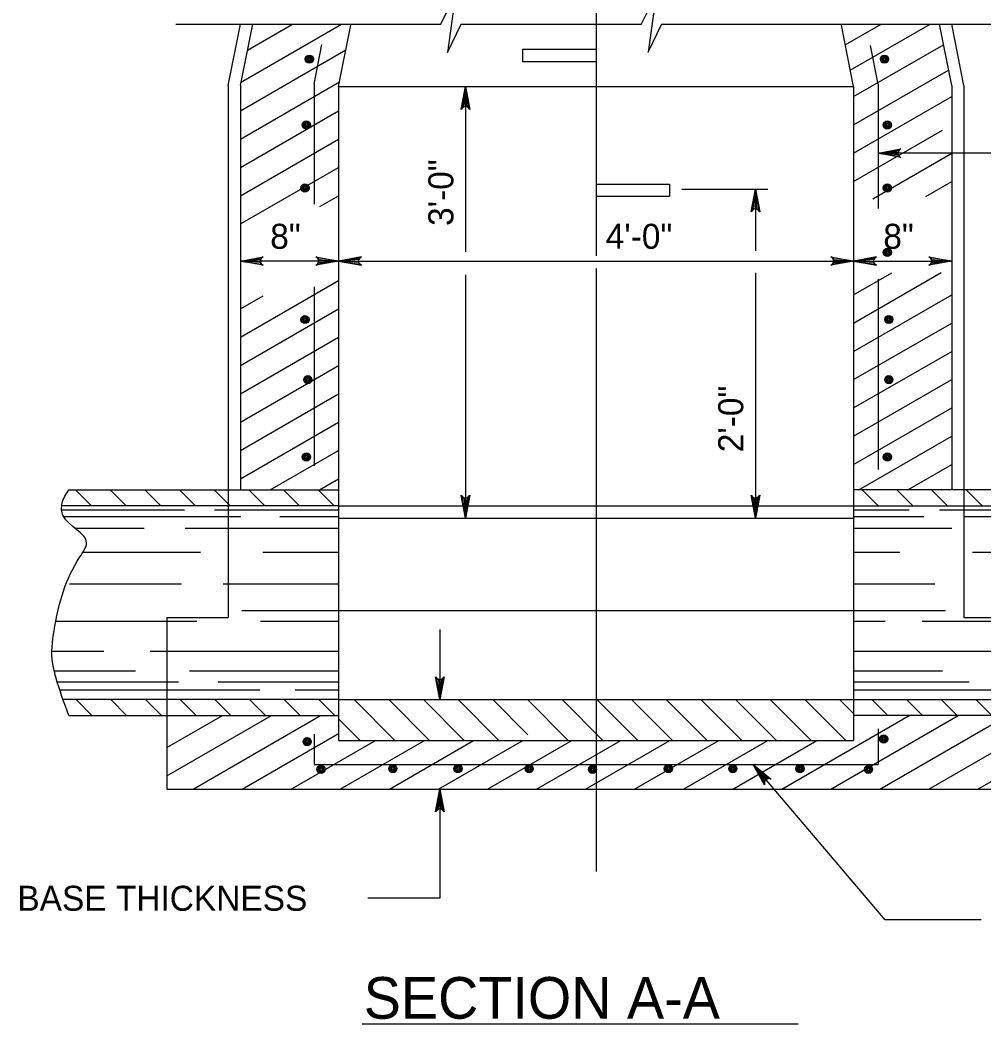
# Model space of a CAD drawing. Extents: x 0.9 to 8, y -0.9 to 9.3.
# Drawn here: x 1.252 to 3.564, y 1.04 to 3.449 of the extents above; entities that cross this region are included whole.
import ezdxf

# ---------------------------------------------------------------- set-up
doc = ezdxf.new("R2010")
doc.units = 0
for name, color, linetype in [('DETL-DIMS', 7, 'Continuous'), ('DETL-LINE', 7, 'Continuous'), ('DETL-NOTE', 7, 'Continuous'), ('DETL-PATT', 7, 'Continuous'), ('DETL-TITL', 7, 'Continuous')]:
    doc.layers.add(name, color=color, linetype=linetype)

msp = doc.modelspace()

# ---------------------------------------------------------------- linework, layer by layer
at = {"layer": 'DETL-DIMS'}
for p, q in [((2.6337, 4.5047), (2.6337, 2.8837)), ((2.3208, 3.2898), (2.3208, 2.8934)), ((3.7703, 3.1298), (3.3102, 3.1298)), ((2.8396, 3.0438), (3.0455, 3.0438)), ((3.0161, 3.0438), (3.0161, 2.8954)), ((2.0161, 2.871), (1.7808, 2.871)), ((2.0161, 2.871), (3.2514, 2.871)), ((3.2514, 2.871), (3.4867, 2.871)), ((2.6337, 2.8532), (2.6337, 1.4062)), ((2.3208, 2.8379), (2.3208, 2.2544)), ((3.0161, 2.8426), (3.0161, 2.2544)), ((1.7843, 2.0325), (3.4722, 2.0325)), ((2.2591, 1.9865), (2.2591, 1.8187)), ((3.3274, 1.29), (3.0102, 1.6628)), ((2.2591, 1.604), (2.2591, 1.3419)), ((2.2591, 1.3419), (2.0865, 1.3419)), ((3.5574, 1.29), (3.3274, 1.29))]:
    msp.add_line(p, q, dxfattribs=at)
for points in [[(2.3208, 3.2898), (2.3311, 3.2349), (2.3281, 3.2392), (2.3245, 3.2413), (2.3208, 3.242), (2.3171, 3.2413), (2.3134, 3.2392), (2.3105, 3.2349), (2.3208, 3.2898), (2.3134, 3.2392), (2.3171, 3.2413), (2.3208, 3.2898), (2.3208, 3.242), (2.3245, 3.2413), (2.3208, 3.2898), (2.3281, 3.2392)], [(3.3102, 3.1298), (3.365, 3.14), (3.3608, 3.1371), (3.3586, 3.1334), (3.358, 3.1298), (3.3586, 3.1261), (3.3608, 3.1224), (3.365, 3.1195), (3.3102, 3.1298), (3.3608, 3.1224), (3.3586, 3.1261), (3.3102, 3.1298), (3.358, 3.1298), (3.3586, 3.1334), (3.3102, 3.1298), (3.3608, 3.1371)], [(3.0161, 3.0438), (3.0264, 2.9889), (3.0234, 2.9932), (3.0197, 2.9953), (3.0161, 2.996), (3.0124, 2.9953), (3.0087, 2.9932), (3.0058, 2.9889), (3.0161, 3.0438), (3.0087, 2.9932), (3.0124, 2.9953), (3.0161, 3.0438), (3.0161, 2.996), (3.0197, 2.9953), (3.0161, 3.0438), (3.0234, 2.9932)], [(1.7808, 2.871), (1.8356, 2.8813), (1.8314, 2.8784), (1.8292, 2.8747), (1.8286, 2.871), (1.8292, 2.8674), (1.8314, 2.8637), (1.8356, 2.8608), (1.7808, 2.871), (1.8314, 2.8637), (1.8292, 2.8674), (1.7808, 2.871), (1.8286, 2.871), (1.8292, 2.8747), (1.7808, 2.871), (1.8314, 2.8784)], [(2.0161, 2.871), (1.9612, 2.8608), (1.9655, 2.8637), (1.9676, 2.8674), (1.9683, 2.871), (1.9676, 2.8747), (1.9655, 2.8784), (1.9612, 2.8813), (2.0161, 2.871), (1.9655, 2.8784), (1.9676, 2.8747), (2.0161, 2.871), (1.9683, 2.871), (1.9676, 2.8674), (2.0161, 2.871), (1.9655, 2.8637)], [(2.0161, 2.871), (2.0709, 2.8608), (2.0667, 2.8637), (2.0645, 2.8674), (2.0639, 2.871), (2.0645, 2.8747), (2.0667, 2.8784), (2.0709, 2.8813), (2.0161, 2.871), (2.0667, 2.8784), (2.0645, 2.8747), (2.0161, 2.871), (2.0639, 2.871), (2.0645, 2.8674), (2.0161, 2.871), (2.0667, 2.8637)], [(3.2514, 2.871), (3.1965, 2.8608), (3.2008, 2.8637), (3.2029, 2.8674), (3.2036, 2.871), (3.2029, 2.8747), (3.2008, 2.8784), (3.1965, 2.8813), (3.2514, 2.871), (3.2008, 2.8784), (3.2029, 2.8747), (3.2514, 2.871), (3.2036, 2.871), (3.2029, 2.8674), (3.2514, 2.871), (3.2008, 2.8637)], [(3.2514, 2.871), (3.3062, 2.8608), (3.302, 2.8637), (3.2998, 2.8674), (3.2992, 2.871), (3.2998, 2.8747), (3.302, 2.8784), (3.3062, 2.8813), (3.2514, 2.871), (3.302, 2.8784), (3.2998, 2.8747), (3.2514, 2.871), (3.2992, 2.871), (3.2998, 2.8674), (3.2514, 2.871), (3.302, 2.8637)], [(3.4867, 2.871), (3.4318, 2.8608), (3.4361, 2.8637), (3.4382, 2.8674), (3.4389, 2.871), (3.4382, 2.8747), (3.4361, 2.8784), (3.4318, 2.8813), (3.4867, 2.871), (3.4361, 2.8784), (3.4382, 2.8747), (3.4867, 2.871), (3.4389, 2.871), (3.4382, 2.8674), (3.4867, 2.871), (3.4361, 2.8637)], [(2.3208, 2.2544), (2.3105, 2.3093), (2.3134, 2.305), (2.3171, 2.3029), (2.3208, 2.3022), (2.3245, 2.3029), (2.3281, 2.305), (2.3311, 2.3093), (2.3208, 2.2544), (2.3281, 2.305), (2.3245, 2.3029), (2.3208, 2.2544), (2.3208, 2.3022), (2.3171, 2.3029), (2.3208, 2.2544), (2.3134, 2.305)], [(3.0161, 2.2544), (3.0058, 2.3093), (3.0087, 2.305), (3.0124, 2.3029), (3.0161, 2.3022), (3.0197, 2.3029), (3.0234, 2.305), (3.0264, 2.3093), (3.0161, 2.2544), (3.0234, 2.305), (3.0197, 2.3029), (3.0161, 2.2544), (3.0161, 2.3022), (3.0124, 2.3029), (3.0161, 2.2544), (3.0087, 2.305)], [(2.2591, 1.8187), (2.2489, 1.8735), (2.2518, 1.8693), (2.2555, 1.8671), (2.2591, 1.8665), (2.2628, 1.8671), (2.2665, 1.8693), (2.2694, 1.8735), (2.2591, 1.8187), (2.2665, 1.8693), (2.2628, 1.8671), (2.2591, 1.8187), (2.2591, 1.8665), (2.2555, 1.8671), (2.2591, 1.8187), (2.2518, 1.8693)], [(3.0102, 1.6628), (3.0536, 1.6277), (3.0486, 1.629), (3.0444, 1.6283), (3.0412, 1.6264), (3.0388, 1.6235), (3.0374, 1.6195), (3.0379, 1.6144), (3.0102, 1.6628), (3.0374, 1.6195), (3.0388, 1.6235), (3.0102, 1.6628), (3.0412, 1.6264), (3.0444, 1.6283), (3.0102, 1.6628), (3.0486, 1.629)], [(2.2591, 1.604), (2.2694, 1.5491), (2.2665, 1.5534), (2.2628, 1.5555), (2.2591, 1.5562), (2.2555, 1.5555), (2.2518, 1.5534), (2.2489, 1.5491), (2.2591, 1.604), (2.2518, 1.5534), (2.2555, 1.5555), (2.2591, 1.604), (2.2591, 1.5562), (2.2628, 1.5555), (2.2591, 1.604), (2.2665, 1.5534)]]:
    msp.add_lwpolyline(points, dxfattribs=at)
at = {"layer": 'DETL-LINE'}
for p, q in [((1.626, 3.4397), (2.2612, 3.4397)), ((1.7514, 3.2927), (1.7808, 3.4397)), ((1.7808, 3.2927), (1.8102, 3.4397)), ((2.0161, 3.2898), (2.0455, 3.4368)), ((2.3097, 3.4397), (2.7427, 3.4397)), ((2.7912, 3.4397), (3.6474, 3.4397)), ((3.2514, 3.2898), (3.222, 3.4368)), ((3.4867, 3.2927), (3.4572, 3.4397)), ((3.5161, 3.2927), (3.4867, 3.4397)), ((1.9572, 3.2956), (1.9763, 3.391)), ((2.4572, 3.3795), (2.4572, 3.35)), ((2.4572, 3.3795), (2.6337, 3.3795)), ((2.6337, 3.3795), (2.6337, 3.35)), ((3.3102, 3.2956), (3.2916, 3.3883)), ((2.4572, 3.35), (2.6337, 3.35)), ((1.7514, 3.2927), (1.7514, 2.3221)), ((1.7808, 3.2927), (1.7808, 2.3221)), ((1.9572, 3.2956), (1.9572, 3.0072)), ((2.0161, 3.2898), (2.0161, 1.7206)), ((2.0161, 3.2898), (3.2514, 3.2898)), ((3.2514, 3.2898), (3.2514, 1.7206)), ((3.3102, 3.2956), (3.3102, 2.997)), ((3.4867, 3.2927), (3.4867, 2.3221)), ((3.5161, 3.2927), (3.5161, 2.3221)), ((2.6337, 3.0559), (2.8102, 3.0559)), ((2.6337, 3.0559), (2.6337, 3.0265)), ((2.8102, 3.0559), (2.8102, 3.0265)), ((2.6337, 3.0265), (2.8102, 3.0265)), ((3.3102, 2.8276), (3.3102, 2.371)), ((1.9572, 2.8093), (1.9572, 2.3798)), ((1.369, 2.3221), (2.0161, 2.3221)), ((1.7514, 2.3221), (1.7514, 2.0157)), ((3.8992, 2.3221), (3.2514, 2.3221)), ((3.5161, 2.3221), (3.5161, 2.0157)), ((2.0161, 2.2839), (1.3513, 2.2839)), ((2.0161, 2.2839), (3.2514, 2.2839)), ((3.2514, 2.2839), (3.9149, 2.2839)), ((2.0161, 2.2544), (3.2514, 2.2544)), ((1.6043, 2.0157), (1.7514, 2.0157)), ((1.6043, 2.0157), (1.6043, 1.7804)), ((3.5161, 2.0157), (3.6631, 2.0157)), ((2.0161, 1.8187), (1.3562, 1.8187)), ((2.0161, 1.8187), (3.2514, 1.8187)), ((3.2514, 1.8187), (3.9113, 1.8187)), ((1.369, 1.7804), (2.0161, 1.7804)), ((1.6043, 1.7804), (1.6043, 1.604)), ((3.8984, 1.7804), (3.2514, 1.7804)), ((1.9572, 1.7354), (1.9572, 1.6628)), ((3.3102, 1.7487), (3.3102, 1.6628)), ((2.0161, 1.7206), (3.2514, 1.7206)), ((1.9572, 1.6628), (3.3102, 1.6628)), ((1.6043, 1.604), (3.6631, 1.604))]:
    msp.add_line(p, q, dxfattribs=at)
for points in [[(2.2612, 3.4398), (2.2962, 3.5113), (2.2772, 3.3714), (2.3098, 3.4398)], [(2.743, 3.4404), (2.778, 3.5118), (2.759, 3.3719), (2.7915, 3.4404)]]:
    msp.add_lwpolyline(points, dxfattribs=at)
for centre, radius in [((1.9458, 3.3556), 0.0098), ((1.9458, 3.3556), 0.00735), ((1.9458, 3.3556), 0.0049), ((1.9458, 3.3556), 0.00245), ((3.3256, 3.3556), 0.0098), ((3.3256, 3.3556), 0.00735), ((3.3256, 3.3556), 0.0049), ((3.3256, 3.3556), 0.00245), ((1.9389, 3.1976), 0.0098), ((1.9389, 3.1976), 0.00735), ((3.3324, 3.1976), 0.0098), ((3.3324, 3.1976), 0.00735), ((1.9389, 3.1976), 0.0049), ((1.9389, 3.1976), 0.00245), ((3.3324, 3.1976), 0.0049), ((3.3324, 3.1976), 0.00245), ((1.9355, 3.0465), 0.0098), ((1.9355, 3.0465), 0.00735), ((1.9355, 3.0465), 0.0049), ((1.9355, 3.0465), 0.00245), ((3.3324, 3.0465), 0.0098), ((3.3324, 3.0465), 0.00735), ((3.3324, 3.0465), 0.0049), ((3.3324, 3.0465), 0.00245), ((3.3324, 2.892), 0.0098), ((3.3324, 2.892), 0.00735), ((3.3324, 2.892), 0.0049), ((3.3324, 2.892), 0.00245), ((1.9355, 2.7306), 0.0098), ((1.9355, 2.7306), 0.00735), ((1.9355, 2.7306), 0.0049), ((1.9355, 2.7306), 0.00245), ((3.3359, 2.7306), 0.0098), ((3.3359, 2.7306), 0.00735), ((3.3359, 2.7306), 0.0049), ((3.3359, 2.7306), 0.00245), ((1.9424, 2.5863), 0.0098), ((1.9424, 2.5863), 0.00735), ((1.9424, 2.5863), 0.0049), ((1.9424, 2.5863), 0.00245), ((3.3359, 2.5863), 0.0098), ((3.3359, 2.5863), 0.00735), ((3.3359, 2.5863), 0.0049), ((3.3359, 2.5863), 0.00245), ((1.9389, 2.4009), 0.0098), ((3.3324, 2.4009), 0.0098), ((1.9389, 2.4009), 0.00735), ((1.9389, 2.4009), 0.0049), ((1.9389, 2.4009), 0.00245), ((3.3324, 2.4009), 0.00735), ((3.3324, 2.4009), 0.0049), ((3.3324, 2.4009), 0.00245), ((1.9408, 1.7178), 0.0098), ((1.9408, 1.7178), 0.00735), ((1.9408, 1.7178), 0.0049), ((1.9408, 1.7178), 0.00245), ((3.3237, 1.7241), 0.0098), ((3.3237, 1.7241), 0.00735), ((3.3237, 1.7241), 0.0049), ((3.3237, 1.7241), 0.00245), ((2.1462, 1.6529), 0.0098), ((2.3027, 1.6529), 0.0098), ((2.4734, 1.6529), 0.0098), ((2.8069, 1.6529), 0.0098), ((2.9617, 1.6529), 0.0098), ((3.123, 1.6529), 0.0098), ((1.974, 1.6513), 0.0098), ((1.974, 1.6513), 0.00735), ((1.974, 1.6513), 0.0049), ((1.974, 1.6513), 0.00245), ((2.1462, 1.6529), 0.00735), ((2.1462, 1.6529), 0.0049), ((2.1462, 1.6529), 0.00245), ((2.3027, 1.6529), 0.00735), ((2.3027, 1.6529), 0.0049), ((2.3027, 1.6529), 0.00245), ((2.4734, 1.6529), 0.00735), ((2.4734, 1.6529), 0.0049), ((2.4734, 1.6529), 0.00245), ((2.6251, 1.6513), 0.0098), ((2.6251, 1.6513), 0.00735), ((2.6251, 1.6513), 0.0049), ((2.6251, 1.6513), 0.00245), ((2.8069, 1.6529), 0.00735), ((2.8069, 1.6529), 0.0049), ((2.8069, 1.6529), 0.00245), ((2.9617, 1.6529), 0.00735), ((2.9617, 1.6529), 0.0049), ((2.9617, 1.6529), 0.00245), ((3.123, 1.6529), 0.00735), ((3.123, 1.6529), 0.0049), ((3.123, 1.6529), 0.00245), ((3.2873, 1.6513), 0.0098), ((3.2873, 1.6513), 0.00735), ((3.2873, 1.6513), 0.0049), ((3.2873, 1.6513), 0.00245)]:
    msp.add_circle(centre, radius, dxfattribs=at)
msp.add_spline([(1.369, 1.7804), (1.3381, 1.8724), (1.3293, 1.9149), (1.3356, 1.9949), (1.3956, 2.1612), (1.4118, 2.1949), (1.3556, 2.2599), (1.3531, 2.2899), (1.369, 2.3221)], degree=3, dxfattribs=at)
at = {"layer": 'DETL-PATT'}
for p, q in [((1.7808, 3.2996), (2.0235, 3.4397)), ((1.7977, 3.3773), (1.9059, 3.4397)), ((3.2313, 3.3899), (3.3176, 3.4397)), ((3.2435, 3.329), (3.4353, 3.4397)), ((1.7808, 3.2317), (2.0337, 3.3777)), ((3.2514, 3.2656), (3.4672, 3.3902)), ((3.2514, 3.1977), (3.4793, 3.3293)), ((1.7808, 3.1638), (2.0183, 3.3009)), ((3.2514, 3.1298), (3.4867, 3.2656)), ((1.7808, 3.0958), (2.0161, 3.2317)), ((3.2514, 3.0619), (3.4647, 3.185)), ((1.7808, 3.0279), (2.0161, 3.1638)), ((3.2978, 3.0207), (3.4867, 3.1298)), ((1.7808, 2.96), (2.0161, 3.0958)), ((3.4246, 3.0261), (3.4867, 3.0619)), ((1.9713, 3.0021), (2.0161, 3.0279)), ((3.2514, 2.7223), (3.4615, 2.8436)), ((3.2514, 2.7902), (3.3428, 2.843)), ((1.7808, 2.6883), (2.0161, 2.8241)), ((1.7808, 2.7562), (1.8353, 2.7877)), ((3.2514, 2.6543), (3.4867, 2.7902)), ((1.7808, 2.6204), (2.0161, 2.7562)), ((3.2514, 2.5864), (3.4867, 2.7223)), ((1.7808, 2.5524), (2.0161, 2.6883)), ((3.2514, 2.5185), (3.4867, 2.6543)), ((1.7808, 2.4845), (2.0161, 2.6204)), ((3.2514, 2.4506), (3.4867, 2.5864)), ((1.7808, 2.4166), (2.0161, 2.5524)), ((3.2514, 2.3826), (3.4867, 2.5185)), ((1.7808, 2.3487), (2.0161, 2.4845)), ((3.2641, 2.3221), (3.4867, 2.4506)), ((1.8524, 2.3221), (2.0161, 2.4166)), ((3.3818, 2.3221), (3.4867, 2.3826)), ((1.97, 2.3221), (2.0161, 2.3487)), ((1.3849, 2.3221), (1.4232, 2.2839)), ((1.4681, 2.3221), (1.5064, 2.2839)), ((1.5513, 2.3221), (1.5896, 2.2839)), ((1.6345, 2.3221), (1.6727, 2.2839)), ((1.7177, 2.3221), (1.7559, 2.2839)), ((1.8009, 2.3221), (1.8391, 2.2839)), ((1.8841, 2.3221), (1.9223, 2.2839)), ((1.9673, 2.3221), (2.0055, 2.2839)), ((3.2722, 2.3221), (3.3105, 2.2839)), ((3.3554, 2.3221), (3.3937, 2.2839)), ((3.4386, 2.3221), (3.4768, 2.2839)), ((3.5218, 2.3221), (3.56, 2.2839)), ((1.3518, 2.2742), (1.6465, 2.2742)), ((1.7185, 2.2742), (2.0161, 2.2742)), ((3.2514, 2.2742), (3.3847, 2.2742)), ((3.4578, 2.2742), (3.915, 2.2742)), ((1.3561, 2.2583), (1.7818, 2.2583)), ((1.8749, 2.2583), (2.0161, 2.2583)), ((3.2514, 2.2583), (3.4195, 2.2583)), ((3.5169, 2.2583), (3.9113, 2.2583)), ((1.3853, 2.2302), (1.5499, 2.2302)), ((1.6483, 2.2302), (2.0161, 2.2302)), ((3.2514, 2.2302), (3.4868, 2.2302)), ((1.4008, 2.1722), (1.6851, 2.1722)), ((1.8345, 2.1722), (2.0161, 2.1722)), ((3.2514, 2.1722), (3.3627, 2.1722)), ((3.5366, 2.1722), (3.8647, 2.1722)), ((1.3704, 2.0966), (1.6395, 2.0966)), ((1.7396, 2.0966), (2.0161, 2.0966)), ((3.2514, 2.0966), (3.4462, 2.0966)), ((1.3391, 2.007), (1.6764, 2.007)), ((1.8292, 2.007), (2.0161, 2.007)), ((3.2514, 2.007), (3.3268, 2.007)), ((3.416, 2.007), (3.7372, 2.007)), ((1.328, 1.9349), (1.4533, 1.9349)), ((1.5639, 1.9349), (2.0161, 1.9349)), ((3.2514, 1.9349), (3.6769, 1.9349)), ((1.3339, 1.8875), (1.5288, 1.8875)), ((1.6588, 1.8875), (2.0161, 1.8875)), ((3.2514, 1.8875), (3.4647, 1.8875)), ((1.3419, 1.8611), (1.6324, 1.8611)), ((1.7273, 1.8611), (2.0161, 1.8611)), ((3.2514, 1.8611), (3.5285, 1.8611)), ((1.3484, 1.8418), (1.8274, 1.8418)), ((1.9118, 1.8418), (2.0161, 1.8418)), ((3.2514, 1.8418), (3.772, 1.8418)), ((1.3864, 1.8187), (1.4246, 1.7804)), ((1.4696, 1.8187), (1.5078, 1.7804)), ((1.5527, 1.8187), (1.591, 1.7804)), ((1.6359, 1.8187), (1.6742, 1.7804)), ((1.7191, 1.8187), (1.7574, 1.7804)), ((1.8023, 1.8187), (1.8406, 1.7804)), ((1.8855, 1.8187), (1.9237, 1.7804)), ((1.9687, 1.8187), (2.0069, 1.7804)), ((2.0531, 1.8187), (2.1512, 1.7206)), ((2.1363, 1.8187), (2.2344, 1.7206)), ((2.2195, 1.8187), (2.3175, 1.7206)), ((2.3027, 1.8187), (2.4007, 1.7206)), ((2.3859, 1.8187), (2.4704, 1.7342)), ((2.4691, 1.8187), (2.5671, 1.7206)), ((2.5523, 1.8187), (2.6503, 1.7206)), ((2.6355, 1.8187), (2.7335, 1.7206)), ((2.7186, 1.8187), (2.8167, 1.7206)), ((2.8018, 1.8187), (2.8999, 1.7206)), ((2.885, 1.8187), (2.9831, 1.7206)), ((2.9682, 1.8187), (3.0662, 1.7206)), ((3.0514, 1.8187), (3.1494, 1.7206)), ((3.1346, 1.8187), (3.2326, 1.7206)), ((3.2178, 1.8187), (3.2514, 1.7851)), ((3.2949, 1.8187), (3.3332, 1.7804)), ((3.3781, 1.8187), (3.4164, 1.7804)), ((3.4613, 1.8187), (3.4996, 1.7804)), ((3.5445, 1.8187), (3.5827, 1.7804)), ((1.6043, 1.7034), (1.7377, 1.7804)), ((1.6043, 1.6355), (1.8554, 1.7804)), ((1.6674, 1.604), (1.973, 1.7804)), ((2.0161, 1.7725), (2.068, 1.7206)), ((3.0791, 1.604), (3.3848, 1.7804)), ((3.1968, 1.604), (3.5024, 1.7804)), ((3.3144, 1.604), (3.6201, 1.7804)), ((1.785, 1.604), (2.0161, 1.7374)), ((3.4321, 1.604), (3.6631, 1.7374)), ((1.9027, 1.604), (2.1047, 1.7206)), ((2.0203, 1.604), (2.2224, 1.7206)), ((2.1379, 1.604), (2.34, 1.7206)), ((2.2556, 1.604), (2.4577, 1.7206)), ((2.3732, 1.604), (2.5753, 1.7206)), ((2.4909, 1.604), (2.693, 1.7206)), ((2.6085, 1.604), (2.8106, 1.7206)), ((2.7262, 1.604), (2.9282, 1.7206)), ((2.8438, 1.604), (3.0459, 1.7206)), ((2.9615, 1.604), (3.1635, 1.7206)), ((3.5497, 1.604), (3.6631, 1.6694))]:
    msp.add_line(p, q, dxfattribs=at)
at = {"layer": 'DETL-TITL'}
msp.add_line((2.0725, 1.0403), (3.1187, 1.0403), dxfattribs=at)

# ---------------------------------------------------------------- texts
at = {"layer": 'DETL-NOTE'}
for s, p in [('3\'-0"', (2.2914, 2.9553)), ('2\'-0"', (2.9867, 2.4122))]:
    msp.add_text(s, height=0.06, rotation=90, dxfattribs=at).set_placement(p)
for s, p in [('8"', (1.8521, 2.9004)), ('4\'-0"', (2.6568, 2.9004)), ('8"', (3.3227, 2.9004)), ('BASE THICKNESS', (1.2456, 1.3119))]:
    msp.add_text(s, height=0.06, dxfattribs=at).set_placement(p)
at = {"layer": 'DETL-TITL'}
msp.add_text('SECTION A-A', height=0.1, dxfattribs=at).set_placement((2.0763, 1.0528))

doc.saveas('drawing.dxf')
